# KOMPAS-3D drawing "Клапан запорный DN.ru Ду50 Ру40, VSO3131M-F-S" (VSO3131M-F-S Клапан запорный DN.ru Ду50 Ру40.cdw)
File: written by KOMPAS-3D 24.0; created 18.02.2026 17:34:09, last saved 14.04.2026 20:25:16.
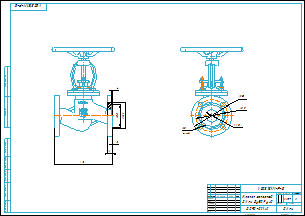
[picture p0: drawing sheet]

Document properties: Автор: R2D2; Форматы листов документа: A2; Полное имя файла: VSO3131M-F-S Клапан запорный DN.ru Ду50 Ру40.m3d; Масса: 11.97; Наименование: Клапан запорный DN.ru Ду50 Ру40; Количество листов документа: 1; Примечание: D090-02142

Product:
- Part/product: Клапан запорный DN.ru Ду50 Ру40  | designation VSO3131M-F-S
    Масса: 11.97
    Раздел спецификации: Прочие изделия
    Форматы листов документа: A2
    Примечание: D090-02142

Views: Проекционный вид 2
Referenced files in E:\Работа\Зайцев\VSO3131M-F-S Клапан запорный DN.ru Ду15-100 Ру40\DN50\: VSO3131M-F-S Клапан запорный DN.ru Ду50 Ру40.m3d
Referenced files in E:\Работа\Зайцев\Для компаса\: чертеж DN.ru А3.cdt
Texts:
  VSO3131M-F-S
  чертеж DN.ru А3.cdt
  Клапан запорный
  DN.ru Ду50 Ру40
  Клапан запорный DN.ru Ду50 Ру40
  VSO3131M-F-S Клапан запорный DN.ru Ду50 Ру40
Dimensions and other numbers on the sheet: 0; 3; 4; 160; 125; 50; 18; 4 отв.; 1:2; 1; 2; 11,97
